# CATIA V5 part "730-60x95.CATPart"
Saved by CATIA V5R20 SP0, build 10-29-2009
Part number: 730-60x95
Definition: NONE
Nomenclature: 730-60x95
Source: Unknown
Description: 730-60x95
Bounding box of the stored display mesh (mm): x -34 to 34, y -33.316 to 33.316, z 0 to 95
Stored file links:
  C:\Users\Utente\Desktop\IO LAVORO\3D X SITO CF\X SITO\730\730-60x95.CATPart
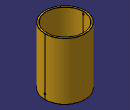
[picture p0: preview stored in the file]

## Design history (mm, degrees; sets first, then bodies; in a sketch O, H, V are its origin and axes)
Body1 "730-60x95" (main body)
  Solid1: solid without history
